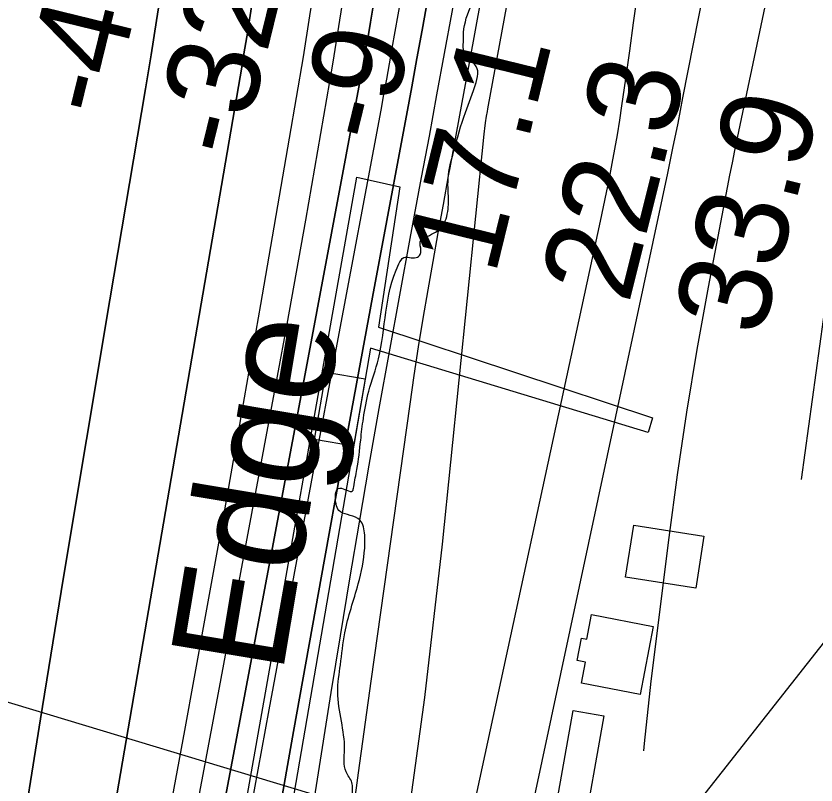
# Model space of a CAD drawing. Extents: x 3297716 to 3335574, y 688621 to 713991.
# Drawn here: x 3324035 to 3324618, y 699056 to 699616 of the extents above; entities that cross this region are included whole.
import ezdxf

# ---------------------------------------------------------------- set-up
doc = ezdxf.new("R2010")
doc.units = 0
for name, color, linetype in [('V-BLDG-OTLN', 7, 'Continuous'), ('V-CHAN-DOCK', 7, 'Continuous'), ('V-RIVR-EDGE', 7, 'Continuous'), ('V-RIVR-IDEN', 7, 'Continuous'), ('V-RIVR-RANG', 7, 'Continuous'), ('V-TOPO-DPTH', 7, 'Continuous'), ('V-TOPO-MAJR', 7, 'Continuous'), ('V-TOPO-MINR', 7, 'Continuous'), ('V-TOPO-WATR', 7, 'Continuous'), ('V-UTIL-LINE', 7, 'Continuous')]:
    doc.layers.add(name, color=color, linetype=linetype)

msp = doc.modelspace()

# ---------------------------------------------------------------- linework, layer by layer
at = {"layer": 'V-BLDG-OTLN'}
for points in [[(3324252.72, 699307.25), (3324261.34, 699356.33), (3324289.7, 699351.35), (3324281.08, 699302.27)], [(3324530.44, 699198.9), (3324479.29, 699206.88), (3324485.21, 699244.87), (3324536.36, 699236.88)], [(3324499.47, 699171.04), (3324489.87, 699121.48), (3324447.11, 699129.76), (3324450.08, 699145.05), (3324444.06, 699146.22), (3324447.21, 699162.49), (3324451.03, 699161.75), (3324454.51, 699179.75)], [(3324424.74, 699018.18), (3324441.11, 699109.88), (3324463.45, 699105.89), (3324447.09, 699014.19)]]:
    msp.add_lwpolyline(points, close=True, dxfattribs=at)
at = {"layer": 'V-CHAN-DOCK'}
for p, q in [((3324180.91, 698918.77), (3324283.7, 699498.16)), ((3324283.7, 699498.16), (3324314.94, 699491.21)), ((3324314.94, 699491.21), (3324299.37, 699389.06)), ((3324299.37, 699389.06), (3324498.78, 699323.03)), ((3324293.56, 699373.71), (3324214.29, 698913.4)), ((3324495.62, 699312.34), (3324293.56, 699373.71)), ((3324498.78, 699323.03), (3324495.62, 699312.34))]:
    msp.add_line(p, q, dxfattribs=at)
at = {"layer": 'V-RIVR-EDGE'}
msp.add_spline([(3322948.37, 694020.91), (3322949.41, 694024.64), (3322957.6, 694042.46), (3322966.99, 694074.23), (3322979.87, 694110.27), (3322999.01, 694165.67), (3323019.31, 694218.75), (3323047.42, 694293.14), (3323064.99, 694340.8), (3323068.52, 694359.79), (3323070.1, 694370.26), (3323070.9, 694381.5), (3323071.35, 694406.32), (3323072.93, 694416.4), (3323078.77, 694426.86), (3323084.23, 694438.86), (3323087.36, 694448.94), (3323090.11, 694465.61), (3323090.52, 694472.2), (3323089.37, 694480.35), (3323089.39, 694485.39), (3323093.68, 694496.24), (3323102.64, 694510.95), (3323113.52, 694521.39), (3323114.31, 694527.21), (3323113.95, 694538.46), (3323114.76, 694553.58), (3323118.7, 694578), (3323123, 694590.01), (3323131.96, 694609.38), (3323139.74, 694619.44), (3323140.92, 694623.32), (3323134.33, 694627.21), (3323134.34, 694629.93), (3323141.36, 694643.48), (3323147.96, 694650.06), (3323149.15, 694657.81), (3323151.89, 694667.5), (3323156.96, 694681.45), (3323161.66, 694700.83), (3323165.59, 694719.43), (3323168.71, 694729.12), (3323174.95, 694741.13), (3323179.24, 694750.42), (3323184.31, 694763.98), (3323190.15, 694773.66), (3323189.4, 694781.42), (3323190.58, 694787.62), (3323200.33, 694810.09), (3323212.42, 694839.92), (3323221.02, 694868.21), (3323223.78, 694883.72), (3323229.64, 694903.09), (3323232.78, 694917.43), (3323234.75, 694930.61), (3323239.05, 694944.56), (3323242.18, 694953.48), (3323245.7, 694968.98), (3323248.84, 694981.38), (3323256.25, 695000.75), (3323259.37, 695006.95), (3323262.1, 695010.82), (3323260.96, 695021.3), (3323261.37, 695030.6), (3323262.55, 695039.52), (3323266.06, 695047.27), (3323266.46, 695051.92), (3323266.11, 695067.04), (3323267.32, 695083.33), (3323269.69, 695102.71), (3323271.27, 695115.51), (3323274.79, 695125.97), (3323280.23, 695129.83), (3323284.9, 695138.35), (3323287.26, 695149.21), (3323288.84, 695163.55), (3323288.86, 695169.37), (3323285.76, 695172.48), (3323285.77, 695176.74), (3323290.06, 695184.1), (3323291.24, 695191.85), (3323304.11, 695221.68), (3323311.14, 695239.5), (3323319.76, 695275.55), (3323326.06, 695314.31), (3323328.49, 695355.8), (3323328.18, 695389.54), (3323328.99, 695403.5), (3323333.29, 695415.9), (3323336.8, 695424.81), (3323336.82, 695432.18), (3323336.83, 695436.45), (3323334.51, 695438), (3323333.74, 695441.88), (3323334.15, 695448.47), (3323336.09, 695450.8), (3323336.51, 695462.04), (3323334.97, 695467.47), (3323336.54, 695474.06), (3323337.72, 695483.37), (3323338.9, 695489.57), (3323338.93, 695501.59), (3323339.72, 695508.96), (3323344.38, 695509.33), (3323347.51, 695521.74), (3323348.69, 695527.55), (3323352.18, 695529.48), (3323353.75, 695534.13), (3323353.75, 695535.68), (3323351.81, 695536.85), (3323349.51, 695546.16), (3323347.23, 695564.78), (3323348.42, 695576.03), (3323350.76, 695580.29), (3323348.83, 695584.17), (3323346.13, 695590.77), (3323352.4, 695615.96), (3323351.63, 695618.68), (3323350.47, 695619.84), (3323349.73, 695636.13), (3323350.52, 695641.95), (3323355.58, 695646.59), (3323358.32, 695659.38), (3323360.27, 695663.64), (3323363.37, 695663.24), (3323363.36, 695657.43), (3323367.22, 695648.89), (3323370.32, 695649.65), (3323370.74, 695664), (3323374.25, 695670.59), (3323381.25, 695680.26), (3323382.05, 695687.24), (3323388.7, 695710.88), (3323396.52, 695736.46), (3323397.7, 695745.37), (3323398.5, 695753.52), (3323397.74, 695759.33), (3323393.88, 695765.94), (3323394.28, 695773.69), (3323399.35, 695782.6), (3323407.11, 695785.29), (3323417.97, 695785.27), (3323417.98, 695788.76), (3323420.72, 695801.16), (3323422.29, 695809.3), (3323424.64, 695816.66), (3323424.67, 695827.91), (3323425.84, 695831.4), (3323428.56, 695834.1), (3323437.47, 695832.14), (3323439.03, 695835.24), (3323431.68, 695839.53), (3323429.76, 695847.29), (3323429.78, 695857.37), (3323430.59, 695869.78), (3323433.7, 695875.97), (3323435.27, 695879.85), (3323433.73, 695887.61), (3323434.91, 695893.03), (3323438.41, 695898.84), (3323445.8, 695905.81), (3323452.79, 695910.44), (3323454.35, 695912.76), (3323453.2, 695917.42), (3323447.39, 695922.86), (3323447.4, 695927.52), (3323447.42, 695932.17), (3323452.11, 695947.28), (3323456.04, 695967.44), (3323463.06, 695984.49), (3323466.95, 695989.52), (3323475.1, 695994.15), (3323476.28, 695998.03), (3323476.29, 696003.84), (3323479.02, 696010.43), (3323484.86, 696018.95), (3323492.25, 696027.07), (3323500.41, 696034.42), (3323505.87, 696046.82), (3323508.98, 696051.46), (3323516.36, 696056.49), (3323519.48, 696063.07), (3323526.09, 696068.1), (3323531.54, 696076.23), (3323536.21, 696085.52), (3323536.23, 696090.56), (3323531.98, 696097.94), (3323530.44, 696102.21), (3323530.44, 696104.54), (3323533.94, 696106.86), (3323544.08, 696129.32), (3323548.75, 696135.91), (3323553.44, 696149.85), (3323555.4, 696157.99), (3323554.64, 696165.36), (3323556.59, 696170.4), (3323558.15, 696173.89), (3323559.71, 696179.31), (3323566.35, 696195.2), (3323569.86, 696204.88), (3323570.27, 696214.19), (3323571.83, 696217.29), (3323578.04, 696218.05), (3323583.09, 696221.14), (3323583.88, 696229.28), (3323588.56, 696240.9), (3323595.18, 696250.19), (3323599.46, 696254.45), (3323606.44, 696256.76), (3323608.79, 696263.34), (3323619.36, 696304.04), (3323636.95, 696361), (3323653.4, 696425.72), (3323674.53, 696502.84), (3323685.09, 696538.5), (3323701.1, 696582.28), (3323710.87, 696613.67), (3323717.16, 696648.16), (3323723.85, 696687.32), (3323726.23, 696709.8), (3323735.23, 696743.91), (3323756.71, 696803.96), (3323773.91, 696858.99), (3323781.36, 696889.99), (3323782.92, 696896.58), (3323786.03, 696898.9), (3323786.43, 696902), (3323784.88, 696905.11), (3323782.18, 696907.83), (3323782.58, 696913.65), (3323780.64, 696915.59), (3323779.09, 696916.37), (3323779.12, 696925.29), (3323780.32, 696940.8), (3323785.4, 696958.24), (3323787.75, 696967.93), (3323789.69, 696967.53), (3323796.28, 696966.74), (3323797.84, 696969.07), (3323798.24, 696973.72), (3323801.39, 696993.88), (3323801.42, 697006.67), (3323801.47, 697025.29), (3323803.45, 697042.73), (3323803.86, 697051.65), (3323803.87, 697055.14), (3323801.16, 697059.03), (3323800.4, 697062.13), (3323801.95, 697063.68), (3323806.99, 697063.67), (3323807.39, 697067.16), (3323807.42, 697077.63), (3323807.83, 697088.48), (3323810.18, 697098.95), (3323812.53, 697109.03), (3323817.96, 697108.63), (3323823.39, 697109.39), (3323824.56, 697110.94), (3323821.47, 697113.66), (3323821.09, 697116.76), (3323819.92, 697117.54), (3323809.85, 697121.06), (3323809.47, 697122.61), (3323809.47, 697125.71), (3323818.44, 697143.91), (3323821.57, 697156.7), (3323825.45, 697157.47), (3323830.88, 697157.84), (3323833.99, 697159.78), (3323833.99, 697162.1), (3323830.12, 697164.05), (3323823.53, 697164.07), (3323823.15, 697167.17), (3323823.16, 697169.89), (3323825.1, 697171.43), (3323827.81, 697171.81), (3323829.37, 697172.2), (3323830.15, 697174.52), (3323831.71, 697179.17), (3323834.04, 697181.88), (3323834.06, 697187.31), (3323836.42, 697202.04), (3323835.27, 697205.92), (3323827.14, 697210.98), (3323823.27, 697216.03), (3323822.89, 697220.3), (3323824.46, 697224.95), (3323826.8, 697233.86), (3323831.48, 697242.77), (3323836.56, 697259.43), (3323841.27, 697282.69), (3323847.54, 697305.94), (3323851.84, 697323), (3323857.31, 697337.72), (3323865.1, 697352.44), (3323867.84, 697363.68), (3323867.09, 697371.43), (3323864.78, 697379.58), (3323867.14, 697391.99), (3323875.35, 697419.5), (3323883.14, 697434.22), (3323896.77, 697457.45), (3323907.28, 697471.78), (3323915.07, 697484.94), (3323917.82, 697500.06), (3323925.64, 697525.64), (3323933.83, 697546.17), (3323940.08, 697560.89), (3323942.03, 697569.03), (3323946.72, 697581.81), (3323953.35, 697596.53), (3323965.83, 697625.59), (3323975.58, 697647.28), (3323979.11, 697663.17), (3323983.41, 697679.06), (3323992.01, 697703.47), (3323996.7, 697721.69), (3324001.77, 697730.98), (3324007.61, 697740.28), (3324011.53, 697757.72), (3324016.23, 697778.26), (3324014.75, 697805.41), (3324012.86, 697825.58), (3324013.66, 697833.72), (3324020.71, 697864.73), (3324032.9, 697932.56), (3324038.39, 697956.98), (3324042.68, 697965.89), (3324046.58, 697972.47), (3324050.87, 697985.26), (3324055.93, 697991.84), (3324055.94, 697996.11), (3324055.57, 698003.47), (3324056.79, 698026.74), (3324061.14, 698060.47), (3324067.83, 698100.78), (3324075.3, 698139.16), (3324081.55, 698157.37), (3324088.56, 698168.6), (3324090.9, 698174.41), (3324094.81, 698187.58), (3324095.62, 698203.87), (3324097.26, 698239.16), (3324100.45, 698272.11), (3324108.32, 698319.4), (3324118.92, 698370.57), (3324132.6, 698414.36), (3324146.34, 698484.13), (3324153, 698511.26), (3324155.74, 698522.11), (3324161.58, 698527.91), (3324167.81, 698539.14), (3324172.5, 698553.09), (3324172.52, 698562.79), (3324169.44, 698571.32), (3324162.1, 698581.81), (3324160.94, 698585.69), (3324160.95, 698588.8), (3324167.25, 698626.4), (3324180.22, 698695.78), (3324201.79, 698795.78), (3324223.7, 698871.35), (3324235.43, 698911.26), (3324246.75, 698941.1), (3324253.02, 698969.39), (3324262.8, 699002.33), (3324270.2, 699013.56), (3324276.82, 699025.95), (3324280.34, 699038.35), (3324280.37, 699048.05), (3324280, 699057.36), (3324275.75, 699065.12), (3324274.63, 699081.41), (3324272.36, 699101.97), (3324269.69, 699123.31), (3324271.68, 699143.08), (3324274.84, 699166.34), (3324284.62, 699202), (3324289.34, 699227.97), (3324288.99, 699240.76), (3324287.45, 699246.2), (3324284.35, 699249.7), (3324270.41, 699255.55), (3324268.48, 699260.21), (3324271.22, 699271.83), (3324280.53, 699269.87), (3324281.31, 699272.58), (3324283.67, 699285.38), (3324286.43, 699306.7), (3324288.41, 699322.59), (3324292.34, 699342.36), (3324299.38, 699366), (3324314.29, 699434.99), (3324317.79, 699439.64), (3324326.71, 699439.61), (3324329.82, 699441.93), (3324329.83, 699448.14), (3324329.84, 699451.24), (3324334.89, 699455.11), (3324345.38, 699462.06), (3324350.06, 699474.85), (3324350.09, 699488.03), (3324350.12, 699497.34), (3324354.04, 699516.72), (3324362.65, 699545.4), (3324370.46, 699567.09), (3324371.64, 699575.62), (3324363.53, 699587.28), (3324361.21, 699591.55), (3324361.22, 699596.2), (3324361.23, 699600.86), (3324374.91, 699641.93), (3324390.56, 699699.28), (3324404.25, 699747.34), (3324408.99, 699779.51), (3324416.85, 699821.77), (3324421.16, 699839.98), (3324418.87, 699854.34), (3324419.28, 699864.03), (3324419.28, 699866.74), (3324416.96, 699867.91), (3324409.6, 699870.65), (3324408.83, 699872.59), (3324409.61, 699875.69), (3324415.07, 699888.86), (3324417.05, 699903.59), (3324417.07, 699913.29), (3324415.15, 699920.66), (3324412.45, 699924.16), (3324416.75, 699940.82), (3324421.01, 699938.1), (3324424.94, 699958.64), (3324426.96, 699990.05), (3324429.73, 700014.86), (3324433.69, 700045.87), (3324439.59, 700081.15), (3324442.78, 700115.27), (3324446.29, 700122.63), (3324447.08, 700129.22), (3324446.74, 700149.77), (3324449.53, 700177.3), (3324457, 700218.78), (3324465.22, 700252.49), (3324468.77, 700274.98), (3324468.83, 700299.02), (3324471.64, 700338.57), (3324481.49, 700399.43), (3324496.05, 700487.82), (3324505.13, 700552.56), (3324518.17, 700651.03), (3324528.84, 700729.34), (3324548.86, 700827.01), (3324554.75, 700855.69), (3324559.02, 700860.73), (3324565.25, 700868.08), (3324568.38, 700880.09), (3324568.39, 700885.13), (3324563.75, 700891.35), (3324563.38, 700895.23), (3324563.38, 700898.72), (3324568.09, 700920.04), (3324578.25, 700949.87), (3324578.66, 700961.89), (3324576.78, 700982.06), (3324579.56, 701010.37), (3324583.11, 701034.01), (3324587.78, 701040.98), (3324591.28, 701043.69), (3324604.47, 701048.31), (3324610.3, 701052.56), (3324613.03, 701058.76), (3324615.76, 701066.12), (3324624.77, 701101.78), (3324630.73, 701157.61), (3324636.7, 701222.35), (3324632.93, 701263.47), (3324633.79, 701299.15), (3324636.97, 701329.39), (3324647.96, 701383.26), (3324651.11, 701404.2), (3324653.48, 701421.26), (3324659.38, 701453.43), (3324663.72, 701482.89), (3324662.59, 701496.85), (3324663.01, 701509.65), (3324668.1, 701528.25), (3324671.25, 701548.02), (3324672.06, 701564.7), (3324673.28, 701584.47), (3324678.35, 701598.03), (3324681.13, 701624.78), (3324682.33, 701636.8), (3324688.16, 701645.32), (3324695.94, 701653.83), (3324697.12, 701661.97), (3324700.3, 701692.21)], degree=3, dxfattribs=at)
at = {"layer": 'V-RIVR-RANG'}
msp.add_line((3324791.29, 698886.28), (3323738.04, 699203.55), dxfattribs=at)
at = {"layer": 'V-TOPO-DPTH'}
for points in [[(3324412.28, 700344.74), (3324335.38, 699865.65), (3324328.53, 699823.19), (3324321.63, 699780.74), (3324314.67, 699738.3), (3324307.67, 699695.86), (3324296.57, 699628.94), (3324295.06, 699619.97), (3324293.54, 699611.01), (3324291.99, 699602.05), (3324290.41, 699593.1), (3324287.9, 699578.94), (3324287.23, 699575.2), (3324286.54, 699571.46), (3324243.7, 699343.25), (3324221.91, 699227.28), (3324200.08, 699111.32), (3324178.21, 698995.37)], [(3324412.28, 700344.74), (3324335.38, 699865.65), (3324328.53, 699823.19), (3324321.63, 699780.74), (3324314.67, 699738.3), (3324307.67, 699695.86), (3324296.57, 699628.94), (3324295.06, 699619.97), (3324293.54, 699611.01), (3324291.99, 699602.05), (3324290.41, 699593.1), (3324287.9, 699578.94), (3324287.23, 699575.2), (3324286.54, 699571.46), (3324243.7, 699343.25), (3324221.91, 699227.28), (3324200.08, 699111.32), (3324178.21, 698995.37)], [(3324275.82, 698997.46), (3324284.91, 699064.34), (3324294.15, 699131.2), (3324322.39, 699332.86), (3324325.41, 699353.72), (3324328.58, 699374.55), (3324331.95, 699395.35), (3324335.45, 699416.13), (3324339.11, 699436.88), (3324342.81, 699457.63), (3324346.59, 699478.36), (3324350.42, 699499.08), (3324351.54, 699505.08), (3324355.96, 699528.8), (3324360.35, 699552.53), (3324364.72, 699576.25), (3324369.06, 699599.99), (3324482.98, 700225.32)], [(3324226.4, 699031.15), (3324237.61, 699094.49), (3324248.86, 699157.82), (3324260.23, 699221.14), (3324271.7, 699284.43), (3324283.34, 699347.69), (3324295.09, 699410.93), (3324316, 699522.61), (3324319.84, 699543.25), (3324323.64, 699563.9), (3324327.4, 699584.56), (3324331.12, 699605.23), (3324359.62, 699764.55), (3324377.32, 699864.92), (3324394.67, 699965.35), (3324411.51, 700065.87)], [(3324411.51, 700065.87), (3324394.67, 699965.35), (3324377.32, 699864.92), (3324359.62, 699764.55), (3324331.12, 699605.23), (3324327.4, 699584.56), (3324323.64, 699563.9), (3324319.84, 699543.25), (3324316, 699522.61), (3324295.09, 699410.93), (3324283.34, 699347.69), (3324271.7, 699284.43), (3324260.23, 699221.14), (3324248.86, 699157.82), (3324237.61, 699094.49), (3324226.4, 699031.15)], [(3324036.95, 699001.86), (3324053.32, 699103.66), (3324069.88, 699205.43), (3324086.73, 699307.14), (3324103.78, 699408.83), (3324129.79, 699562.67), (3324133.89, 699587.43), (3324137.86, 699612.21), (3324141.66, 699637.01), (3324145.35, 699661.84), (3324164.18, 699792.04), (3324176.95, 699882.01), (3324189.38, 699972.03), (3324201.31, 700062.12)], [(3324201.31, 700062.12), (3324189.38, 699972.03), (3324176.95, 699882.01), (3324164.18, 699792.04), (3324145.35, 699661.84), (3324141.66, 699637.01), (3324137.86, 699612.21), (3324133.89, 699587.43), (3324129.79, 699562.67), (3324103.78, 699408.83), (3324086.73, 699307.14), (3324069.88, 699205.43), (3324053.32, 699103.66), (3324036.95, 699001.86)], [(3324144, 699017.91), (3324158.38, 699095.34), (3324172.52, 699172.82), (3324186.48, 699250.32), (3324200.2, 699327.87), (3324213.74, 699405.46), (3324234.69, 699526.6), (3324239.74, 699556.25), (3324244.7, 699585.92), (3324249.49, 699615.62), (3324254.19, 699645.34), (3324281.45, 699820.65), (3324299.36, 699938.09), (3324316.8, 700055.59)], [(3324144, 699017.91), (3324158.38, 699095.34), (3324172.52, 699172.82), (3324186.48, 699250.32), (3324200.2, 699327.87), (3324213.74, 699405.46), (3324234.69, 699526.6), (3324239.74, 699556.25), (3324244.7, 699585.92), (3324249.49, 699615.62), (3324254.19, 699645.34), (3324281.45, 699820.65), (3324299.36, 699938.09), (3324316.8, 700055.59)], [(3324257.31, 700000.45), (3324250.72, 699945.83), (3324243.97, 699891.22), (3324237.11, 699836.63), (3324231.61, 699793.31), (3324227.3, 699760.4), (3324222.8, 699727.53), (3324218.03, 699694.69), (3324213.07, 699661.87), (3324205.47, 699612.93), (3324204.16, 699604.61), (3324202.82, 699596.3), (3324201.45, 699587.99), (3324200.04, 699579.69), (3324095.26, 698969.3)], [(3324257.31, 700000.45), (3324250.72, 699945.83), (3324243.97, 699891.22), (3324237.11, 699836.63), (3324231.61, 699793.31), (3324227.3, 699760.4), (3324222.8, 699727.53), (3324218.03, 699694.69), (3324213.07, 699661.87), (3324205.47, 699612.93), (3324204.16, 699604.61), (3324202.82, 699596.3), (3324201.45, 699587.99), (3324200.04, 699579.69), (3324095.26, 698969.3)]]:
    msp.add_lwpolyline(points, dxfattribs=at)
at = {"layer": 'V-TOPO-MAJR'}
msp.add_lwpolyline([(3324364.96, 698821.8), (3324506.14, 699482.93), (3324509.98, 699501.15), (3324513.76, 699519.39), (3324517.45, 699537.64), (3324521.08, 699555.91), (3324556.04, 699734.48), (3324576.17, 699842.19), (3324595.07, 699950.12), (3324612.1, 700058.35)], dxfattribs=at)
at = {"layer": 'V-TOPO-MINR'}
for points in [[(3324203.87, 699022.95), (3324219.89, 699110.4), (3324236, 699197.84), (3324252.23, 699285.26), (3324268.55, 699372.66), (3324301.24, 699547.08), (3324303.32, 699558.32), (3324305.39, 699569.56), (3324307.43, 699580.81), (3324309.44, 699592.06), (3324324.56, 699677.3), (3324334.02, 699731.19), (3324343.34, 699785.1), (3324352.47, 699839.05), (3324361.47, 699893.02), (3324476.31, 700589.99), (3324476.86, 700593.4), (3324477.38, 700596.82), (3324479.72, 700612.75), (3324481.14, 700622.43), (3324482.54, 700632.11), (3324483.92, 700641.79), (3324485.29, 700651.47), (3324578.03, 701313.17)], [(3324317.93, 699007.82), (3324333.05, 699119.2), (3324346.04, 699230.9), (3324376.44, 699529.63), (3324376.66, 699531.69), (3324376.89, 699533.75), (3324377.38, 699537.86), (3324378.01, 699542.54), (3324378.66, 699546.17), (3324379.02, 699548.11), (3324559.23, 700527.72), (3324560.82, 700536.57), (3324562.35, 700545.43), (3324563.81, 700554.31), (3324565.21, 700563.19), (3324566.52, 700572.09), (3324567.77, 700581), (3324568.92, 700589.92), (3324570.01, 700598.85), (3324651.5, 701301.19)], [(3324164.62, 699025.81), (3324183.59, 699126.55), (3324202.42, 699227.32), (3324225.82, 699353.19), (3324232.79, 699391.05), (3324239.67, 699428.93), (3324246.43, 699466.83), (3324253.11, 699504.74), (3324259.63, 699542.68), (3324266.04, 699580.64), (3324272.26, 699618.63), (3324278.37, 699656.64), (3324341.17, 700053.45), (3324355.41, 700144.58), (3324369.42, 700235.74), (3324383.07, 700326.95), (3324396.49, 700418.2), (3324415.67, 700550.35), (3324419.34, 700575.55), (3324423.03, 700600.75), (3324426.75, 700625.94), (3324430.49, 700651.14), (3324489.47, 701046.94)], [(3324279.49, 698626.5), (3324461.03, 699466.2), (3324463.25, 699476.65), (3324465.43, 699487.12), (3324467.54, 699497.59), (3324469.6, 699508.08), (3324471.54, 699518.59), (3324473.39, 699529.11), (3324475.07, 699539.66), (3324476.64, 699550.23), (3324479.41, 699569.81), (3324482.27, 699590.18), (3324485.09, 699610.56), (3324487.87, 699630.95), (3324490.61, 699651.34), (3324608.31, 700533.42), (3324611, 700554.08), (3324613.59, 700574.75), (3324616.05, 700595.44), (3324618.41, 700616.14), (3324632.29, 700741.47), (3324641.83, 700824.81), (3324651.77, 700908.09), (3324662.32, 700991.31)], [(3324178.21, 698995.37), (3324200.08, 699111.32), (3324221.91, 699227.28), (3324243.7, 699343.25), (3324286.54, 699571.46), (3324287.23, 699575.2), (3324287.9, 699578.94), (3324290.41, 699593.1), (3324291.99, 699602.05), (3324293.54, 699611.01), (3324295.06, 699619.97), (3324296.57, 699628.94), (3324307.67, 699695.86), (3324314.67, 699738.3), (3324321.63, 699780.74), (3324328.53, 699823.19), (3324335.38, 699865.65), (3324412.28, 700344.74)], [(3324275.82, 698997.46), (3324284.91, 699064.34), (3324294.15, 699131.2), (3324322.39, 699332.86), (3324325.41, 699353.72), (3324328.58, 699374.55), (3324331.95, 699395.35), (3324335.45, 699416.13), (3324339.11, 699436.88), (3324342.81, 699457.63), (3324346.59, 699478.36), (3324350.42, 699499.08), (3324351.54, 699505.08), (3324355.96, 699528.8), (3324360.35, 699552.53), (3324364.72, 699576.25), (3324369.06, 699599.99), (3324482.98, 700225.32)], [(3324492.64, 699080.37), (3324493.07, 699085.83), (3324497.85, 699131.19), (3324510.94, 699235.71), (3324517.11, 699281.45), (3324523.86, 699327.1), (3324531.47, 699372.61), (3324539.66, 699418.02), (3324553.47, 699490.59), (3324555.22, 699499.65), (3324557, 699508.71), (3324558.84, 699517.75), (3324560.72, 699526.79), (3324696.8, 700173.56)], [(3324201.31, 700062.12), (3324189.38, 699972.03), (3324176.95, 699882.01), (3324164.18, 699792.04), (3324145.35, 699661.84), (3324141.66, 699637.01), (3324137.86, 699612.21), (3324133.89, 699587.43), (3324129.79, 699562.67), (3324103.78, 699408.83), (3324086.73, 699307.14), (3324069.88, 699205.43), (3324053.32, 699103.66), (3324036.95, 699001.86)], [(3324144, 699017.91), (3324158.38, 699095.34), (3324172.52, 699172.82), (3324186.48, 699250.32), (3324200.2, 699327.87), (3324213.74, 699405.46), (3324234.69, 699526.6), (3324239.74, 699556.25), (3324244.7, 699585.92), (3324249.49, 699615.62), (3324254.19, 699645.34), (3324281.45, 699820.65), (3324299.36, 699938.09), (3324316.8, 700055.59)], [(3324190.3, 698648.88), (3324265.04, 699122.83), (3324271.68, 699164.26), (3324278.46, 699205.67), (3324285.45, 699247.04), (3324292.58, 699288.4), (3324299.89, 699329.72), (3324307.29, 699371.02), (3324314.84, 699412.3), (3324322.48, 699453.56), (3324330.8, 699498.06), (3324336.4, 699528.14), (3324341.96, 699558.22), (3324347.46, 699588.32), (3324352.92, 699618.42), (3324409.92, 699934.24), (3324429.18, 700042.95)], [(3324095.26, 698969.3), (3324200.04, 699579.69), (3324201.45, 699587.99), (3324202.82, 699596.3), (3324204.16, 699604.61), (3324205.47, 699612.93), (3324213.07, 699661.87), (3324218.03, 699694.69), (3324222.8, 699727.53), (3324227.3, 699760.4), (3324231.61, 699793.31), (3324237.11, 699836.63), (3324243.97, 699891.22), (3324250.72, 699945.83), (3324257.31, 700000.45)], [(3324607.36, 699278.12), (3324631.33, 699452.76), (3324634.17, 699470.85), (3324637.48, 699488.85), (3324641.49, 699506.7), (3324645.97, 699524.46), (3324696.29, 699708.86)]]:
    msp.add_lwpolyline(points, dxfattribs=at)
at = {"layer": 'V-TOPO-WATR'}
msp.add_lwpolyline([(3324226.4, 699031.15), (3324237.61, 699094.49), (3324248.86, 699157.82), (3324260.23, 699221.14), (3324271.7, 699284.43), (3324283.34, 699347.69), (3324295.09, 699410.93), (3324316, 699522.61), (3324319.84, 699543.25), (3324323.64, 699563.9), (3324327.4, 699584.56), (3324331.12, 699605.23), (3324359.62, 699764.55), (3324377.32, 699864.92), (3324394.67, 699965.35), (3324411.51, 700065.87)], dxfattribs=at)
at = {"layer": 'V-UTIL-LINE'}
msp.add_lwpolyline([(3325181.19, 699497.54), (3325111.37, 699496.64), (3324794.49, 699376.65), (3324478.66, 698975.39)], dxfattribs=at)

# ---------------------------------------------------------------- texts
at = {"layer": 'V-RIVR-IDEN'}
msp.add_text('Edge', height=83, rotation=80.52814, dxfattribs=at).set_placement((3324229.22, 699134.92))
at = {"layer": 'V-RIVR-RANG'}
for s, rotation, p in [('-47', 76.24894, (3324103.31, 699540.02)), ('-32', 76.24894, (3324198.95, 699510.12)), ('-9', 76.24894, (3324304.49, 699520.7)), ('17.1', 76.24894, (3324384.19, 699425.71)), ('22.3', 75.96833, (3324481.48, 699405.02)), ('33.9', 75.96833, (3324578.49, 699380.75))]:
    msp.add_text(s, height=67, rotation=rotation, dxfattribs=at).set_placement(p)

doc.saveas('drawing.dxf')
